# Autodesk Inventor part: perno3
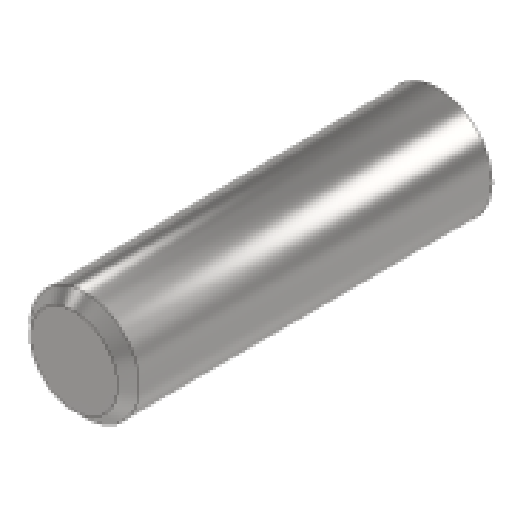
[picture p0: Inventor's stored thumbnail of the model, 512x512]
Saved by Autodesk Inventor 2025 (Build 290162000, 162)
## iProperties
Created: 2025-10
Part Number: perno3
Material: Acciaio inossidabile
Document SubType Name: Modeling
Designer: Ryzen5700u
Density: 8 g/cm^3
Appearance: Semilucidato
Mass: 38.3612 g
Surface Area: 68.2825 cm^2
Volume: 38.3612 cm^3
Author: Ryzen5700u
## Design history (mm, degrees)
node "Piano di lavoro1"
sketch "Schizzo1"
  geometry: C1 r 10 at (0, 0); 1 further point
  constraints: 1 centre point, 1 coincident
  dimensions: "d0" = 20 diameter of C1
extrude "Estrusione1" new body sketch "Schizzo1" distance "d1" = 67; taper "d2" = 0 deg
chamfer "Smusso1" distance "d3" = 2; stored, may be unused: second distance "d4" = 2, angle "d5" = 45 deg
node "Solido1"
